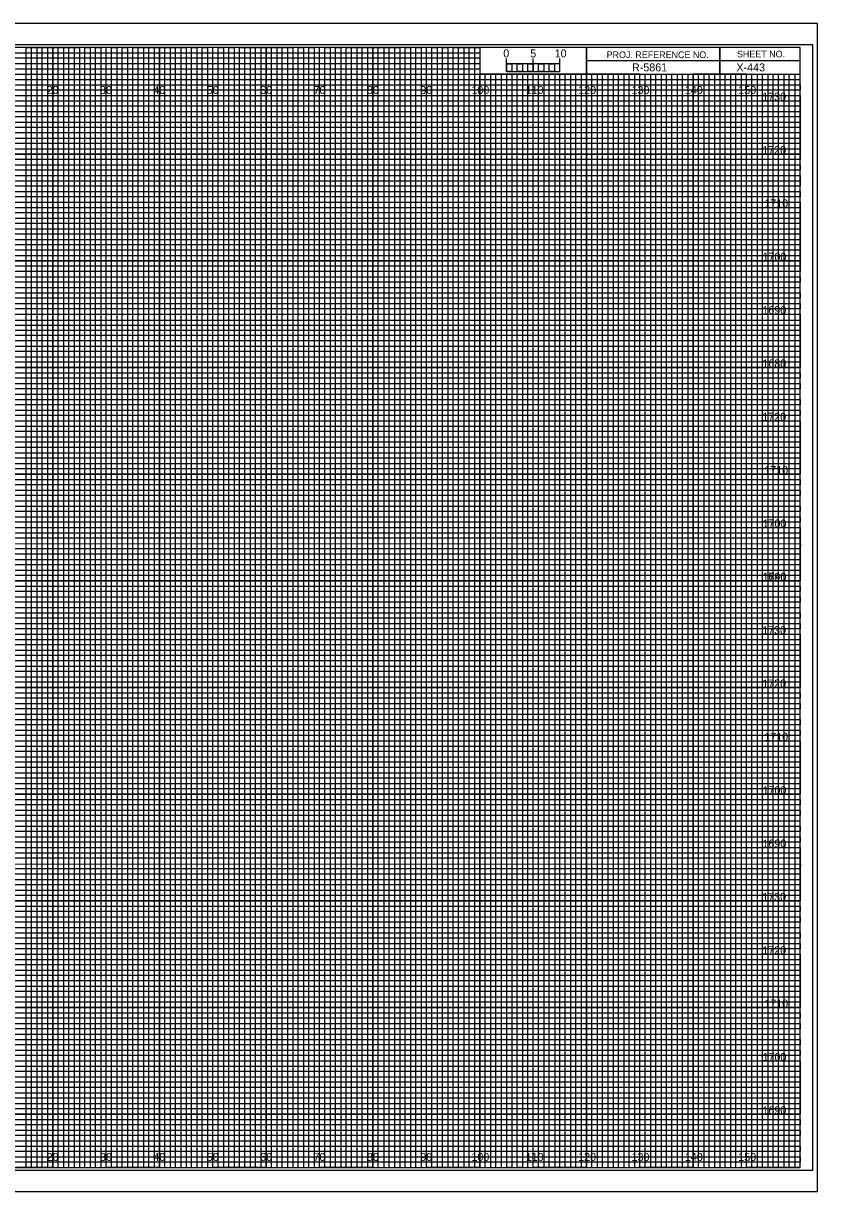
# Model space of a CAD drawing. Extents: x -13 to 323, y -5 to 1314.
# Drawn here: x 174.5 to 323.3, y 435.5 to 654.5 of the extents above; entities that cross this region are included whole.
import ezdxf

# ---------------------------------------------------------------- set-up
doc = ezdxf.new("R2010")
doc.units = 0
for name, color, linetype in [('Prop XS Bar Scale Labels', 7, 'Continuous'), ('Prop XS Project Number', 7, 'Continuous'), ('Prop XS Sheet Number', 7, 'Continuous'), ('Raster_Level_0', 7, 'Continuous'), ('Scratch_Level_3', 7, 'Continuous'), ('Sheet Cross Section CELL', 7, 'Continuous'), ('Sheet Cross Section Grid Major CELL', 7, 'Continuous'), ('Sheet Cross Section Grid Middle CELL', 7, 'Continuous'), ('Sheet Cross Section Grid Minor 1 CELL', 7, 'Continuous'), ('Sheet Cross Section Grid Minor 2 CELL', 7, 'Continuous'), ('Sheet Cross Section Scale CELL', 7, 'Continuous'), ('Sheet Cutting Line CELL', 7, 'Continuous'), ('Sheet DOT Grid CELL', 7, 'Continuous'), ('Sheet Plot Border Inside CELL', 7, 'Continuous'), ('Sheet Plot Border Outside CELL', 7, 'Continuous')]:
    doc.layers.add(name, color=color, linetype=linetype)

msp = doc.modelspace()

# ---------------------------------------------------------------- linework, layer by layer
at = {"layer": 'Sheet Cross Section CELL'}
for p, q in [((305, 650), (305, 645)), ((305, 645), (305, 650)), ((280, 647.5), (280, 645)), ((320, 647.49), (280, 647.49)), ((280, 645), (320, 645))]:
    msp.add_line(p, q, dxfattribs=at)
for points in [[(320, 650), (0, 650), (0, 440), (320, 440)], [(280, 650), (260, 650), (260, 645.03), (280, 645.03)], [(320, 650), (280, 650), (280, 645), (320, 645)]]:
    msp.add_lwpolyline(points, close=True, dxfattribs=at)
at = {"layer": 'Sheet Cross Section Grid Major CELL'}
for p, q in [((190, 650), (180, 650)), ((180, 650), (180, 440)), ((190, 440), (190, 650)), ((210, 650), (200, 650)), ((200, 650), (200, 440)), ((210, 440), (210, 650)), ((230, 650), (220, 650)), ((220, 650), (220, 440)), ((230, 440), (230, 650)), ((250, 650), (240, 650)), ((240, 650), (240, 440)), ((250, 440), (250, 650)), ((260, 650), (260, 440)), ((270, 440), (270, 645)), ((290, 645), (280, 645)), ((280, 645), (280, 440)), ((290, 440), (290, 645)), ((310, 645), (300, 645)), ((300, 645), (300, 440)), ((310, 440), (310, 645)), ((180, 440), (170, 440)), ((200, 440), (190, 440)), ((220, 440), (210, 440)), ((240, 440), (230, 440)), ((260, 440), (250, 440)), ((280, 440), (270, 440)), ((300, 440), (290, 440)), ((320, 440), (310, 440)), ((320, 440), (320, 440))]:
    msp.add_line(p, q, dxfattribs=at)
for points in [[(0, 640), (320, 640), (320, 630), (0, 630)], [(0, 620), (320, 620), (320, 610), (0, 610)], [(0, 600), (320, 600), (320, 590), (0, 590)], [(0, 580), (320, 580), (320, 570), (0, 570)], [(0, 560), (320, 560), (320, 550), (0, 550)], [(0, 540), (320, 540), (320, 530), (0, 530)], [(0, 520), (320, 520), (320, 510), (0, 510)], [(0, 500), (320, 500), (320, 490), (0, 490)], [(0, 480), (320, 480), (320, 470), (0, 470)], [(0, 460), (320, 460), (320, 450), (0, 450)]]:
    msp.add_lwpolyline(points, dxfattribs=at)
at = {"layer": 'Sheet Cross Section Grid Middle CELL'}
for points in [[(165, 440), (175, 440), (175, 650), (185, 650), (185, 440), (195, 440), (195, 650), (205, 650), (205, 440), (215, 440), (215, 650), (225, 650), (225, 440), (235, 440), (235, 650), (245, 650), (245, 440), (255, 440), (255, 650), (259.93, 650), (260, 650), (260, 645), (264.99, 645), (264.99, 440), (275, 440), (275, 645), (285, 645), (285, 440), (295, 440), (295, 645), (305, 645), (305, 440), (315, 440), (315, 645)], [(0, 645), (275, 645)], [(0, 625), (320, 625), (320, 635), (0, 635)], [(0, 605), (320, 605), (320, 615), (0, 615)], [(0, 585), (320, 585), (320, 595), (0, 595)], [(0, 565), (320, 565), (320, 575), (0, 575)], [(0, 545), (320, 545), (320, 555), (0, 555)], [(0, 525), (320, 525), (320, 535), (0, 535)], [(0, 505), (320, 505), (320, 515), (0, 515)], [(0, 485), (320, 485), (320, 495), (0, 495)], [(0, 465), (320, 465), (320, 475), (0, 475)], [(0, 445), (320, 445), (320, 455), (0, 455)]]:
    msp.add_lwpolyline(points, dxfattribs=at)
at = {"layer": 'Sheet Cross Section Grid Minor 1 CELL'}
for p, q in [((0, 649), (260, 649)), ((260, 649), (260, 647.98)), ((260, 647.98), (0, 647.98)), ((0, 647), (260, 647)), ((260, 647), (260, 645.89)), ((260, 645.89), (0, 645.89)), ((0, 644), (320, 644))]:
    msp.add_line(p, q, dxfattribs=at)
for points in [[(0, 643), (270, 643), (320, 643), (320, 642), (0, 642)], [(0, 641), (320, 641), (320, 639), (0, 639)], [(0, 638), (320, 638), (320, 637), (0, 636.98)], [(0, 636), (320, 636), (320, 634), (0, 634)], [(0, 633), (320, 633), (320, 632), (0, 632)], [(0, 631), (320, 631), (320, 629), (0, 629)], [(0, 628), (320, 628), (320, 627), (0, 627)], [(0, 626), (320, 626), (320, 624), (0, 624)], [(0, 623), (320, 623), (320, 622), (0, 622)], [(0, 621), (320, 621), (320, 619), (0, 619)], [(0, 618), (320, 618), (320, 617), (0, 617)], [(0, 616), (320, 616), (320, 613.95), (320, 613), (320, 612), (0, 612)], [(0, 614), (320, 614), (320, 613), (0, 613)], [(0, 611), (320, 611), (320, 609), (0, 609.03)], [(0, 609.03), (320, 609), (320, 608), (0, 608)], [(0, 607), (320, 607), (320, 606), (0, 606)], [(0, 604), (320, 604), (320, 603), (0, 603)], [(0, 602), (320, 602), (320, 601), (0, 601)], [(-0.07, 598.89), (320, 598.89), (320, 597.88), (-0.07, 597.88)], [(0, 597), (320, 597), (320, 596), (0, 596)], [(0, 594), (320, 594), (320, 593), (0, 593)], [(0, 592), (320, 592), (320, 591), (0, 591)], [(0, 589), (320, 589), (320, 588), (0, 588)], [(0, 587), (320, 587), (320, 586), (0, 586)], [(0, 584), (320, 584), (320, 583), (0, 583)], [(0, 582), (320, 582), (320, 581), (0, 581)], [(0, 579), (320, 579), (319.99, 577.98), (0, 578)], [(0, 577), (320, 577), (320, 576), (0, 576)], [(0, 574), (320, 574), (320, 573), (0, 573)], [(0, 572), (320, 572), (320, 571), (0, 571)], [(0, 569), (320, 569), (320, 568), (0, 568)], [(0, 567), (320, 567), (320, 566), (0, 566)], [(0, 564), (320, 564), (320, 563), (0, 563)], [(0, 562), (320, 562), (320, 561), (0, 561)], [(0, 559), (320, 559), (320, 558), (0, 558)], [(0, 556.99), (320.07, 556.91), (320, 556), (0, 556)], [(0, 554), (320, 554), (320, 553), (0, 553)], [(0, 552), (320, 552), (320, 551), (0, 551)], [(0, 549), (320, 549), (320, 548), (0, 548)], [(0, 547), (320, 547), (320, 546), (0, 546)], [(0, 544), (320, 544), (320, 543), (0, 543)], [(0, 542), (320, 542), (320, 541), (0, 541)], [(0, 539), (320, 539), (320, 538), (0, 538)], [(0, 537), (320, 537), (320, 536), (0, 536)], [(0, 534), (320, 534), (320, 533), (0, 533)], [(0, 532), (320, 532), (320, 531), (0, 531)], [(0, 529), (320, 529), (320, 528), (0, 528)], [(0, 527), (320, 527), (320, 526), (0, 526)], [(0, 524), (320, 524), (320, 523), (0, 523)], [(0, 522), (320, 522), (320, 521), (0, 521)], [(0, 519), (320, 519), (319.99, 517.98), (0, 518)], [(0, 517), (320, 517), (320, 516), (0, 516)], [(0, 514), (320, 514), (320, 513), (0, 513)], [(0, 512), (320, 512), (320, 511), (0, 511)], [(0, 509), (320, 509), (320, 508), (0, 508)], [(0, 507), (320, 507), (320, 506), (0, 506)], [(0, 504), (320, 504), (320, 503), (0, 503)], [(0, 502), (320, 502), (320, 501), (0, 501)], [(0, 499), (320, 499), (320, 498), (0, 498)], [(0, 496.99), (320.07, 496.91), (320, 496), (0, 496)], [(0, 494), (320, 494), (320, 493), (0, 493)], [(0, 492), (320, 492), (320, 491), (0, 491)], [(0, 489), (320, 489), (320, 488), (0, 488)], [(0, 487), (320, 487), (320, 486), (0, 486)], [(0, 484), (320, 484), (320, 483), (0, 483)], [(0, 482), (320, 482), (320, 481), (0, 481)], [(0, 479), (320, 479), (320, 478), (0, 478)], [(0, 477), (320, 477), (320, 476), (0, 476)], [(0, 474), (320, 474), (320, 473), (0, 473)], [(0, 472), (320, 472), (320, 471), (0, 471)], [(0, 469), (320, 469), (320, 468), (0, 468)], [(0, 467), (320, 467), (320, 466), (0, 466)], [(0, 464), (320, 464), (320, 463), (0, 463)], [(0, 462), (320, 462), (320, 461), (0, 461)], [(0, 459), (320, 459), (320, 458), (0, 458)], [(0, 457), (320, 457), (320, 456), (0, 456)], [(0, 454), (320, 454), (320, 453), (0, 453)], [(0, 452), (320, 452), (320, 451), (0, 451)], [(0, 449), (320, 449), (320, 448), (0, 448)], [(0, 447), (320, 447), (320, 446), (0, 446)], [(0, 444), (320, 444), (320, 443), (0, 443)], [(0, 442), (320, 442), (320, 441), (0, 441)]]:
    msp.add_lwpolyline(points, dxfattribs=at)
at = {"layer": 'Sheet Cross Section Grid Minor 2 CELL'}
for p, q in [((267, 645), (266.01, 645)), ((266.01, 645), (266.01, 440)), ((267, 440), (267, 645)), ((269, 645), (268, 645)), ((268, 645), (268, 440)), ((269, 440), (269, 645)), ((266.01, 440), (265, 440)), ((268, 440), (267, 440))]:
    msp.add_line(p, q, dxfattribs=at)
for points in [[(175, 440), (176, 440), (176, 650), (177, 650), (177, 440)], [(177, 440), (178, 440), (178, 650), (179, 650), (179, 440)], [(180, 440), (181, 440), (181, 650), (182, 650), (182, 440)], [(182, 440), (183, 440), (183, 650), (184, 650), (184, 440)], [(185, 440), (186, 440), (186, 650), (187, 650), (187, 440)], [(187, 440), (188, 440), (188, 650), (189, 650), (189, 440)], [(190, 440), (191, 440), (191, 650), (192, 650), (192, 440)], [(192, 440), (193, 440), (193, 650), (194, 650), (194, 440)], [(195, 440), (196, 440), (196, 650), (197, 650), (197, 440)], [(197, 440), (198, 440), (198, 650), (199, 650), (199, 440)], [(200, 440), (201, 440), (201, 650), (202, 650), (202, 440)], [(202, 440), (203, 440), (203, 650), (204, 650), (204, 440)], [(205, 440), (206, 440), (206, 650), (207, 650), (207, 440)], [(207, 440), (208, 440), (208, 650), (209, 650), (209, 440)], [(210, 440), (211, 440), (211, 650), (212, 650), (212, 440)], [(212, 440), (213, 440), (213, 650), (214, 650), (214, 440)], [(215, 440), (216, 440), (216, 650), (217, 650), (217, 440)], [(217, 440), (218, 440), (218, 650), (219, 650), (219, 440)], [(220, 440), (221, 440), (221, 650), (222, 650), (222, 440)], [(222, 440), (223, 440), (223, 650), (224, 650), (224, 440)], [(225, 440), (226, 440), (226, 650), (227, 650), (227, 440)], [(227, 440), (228, 440), (228, 650), (229, 650), (229, 440)], [(230, 440), (231, 440), (231, 650), (232, 650), (232, 440)], [(232, 440), (233, 440), (233, 650), (234, 650), (234, 440)], [(235, 440), (236, 440), (236, 650), (237, 650), (237, 440)], [(237, 440), (238, 440), (238, 650), (239, 650), (239, 440)], [(240, 440), (241, 440), (241, 650), (242, 650), (242, 440)], [(242, 440), (243, 440), (243, 650), (244, 650), (244, 440)], [(245, 440), (246, 440), (246, 650), (247, 650), (247, 440)], [(247, 440), (248, 440), (248, 650), (249, 650), (249, 440)], [(250, 440), (251, 440), (251, 650), (252, 650), (252, 440)], [(252, 440), (253, 440), (253, 650), (254, 650), (254, 440)], [(255, 440), (256, 440), (256, 650), (257, 650), (257, 440)], [(257, 440), (258, 440), (258, 650), (259, 650), (259, 440)], [(260, 440), (261, 440), (261, 645), (262.02, 645), (262.02, 440)], [(262, 440), (263, 440), (263, 645), (263.99, 645), (263.99, 440)], [(270, 440), (270.98, 440), (270.98, 645), (272, 645), (272, 440)], [(272, 440), (273, 440), (273, 645), (274.05, 645), (274.05, 440)], [(275, 440), (276, 440), (276, 645), (277, 645), (277, 440)], [(277, 440), (278, 440), (278, 645), (279, 645), (279, 440)], [(280, 440), (281, 440), (281, 645), (282, 645), (282, 440)], [(282, 440), (283, 440), (283, 645), (284, 645), (284, 440)], [(285, 440), (286, 440), (286, 645), (287, 645), (287, 440)], [(287, 440), (288, 440), (288, 645), (289, 645), (289, 440)], [(290, 440), (291, 440), (291, 645), (292, 645), (292, 440)], [(292, 440), (293, 440), (293, 645), (294, 645), (294, 440)], [(295, 440), (296, 440), (296, 645), (297, 645), (297, 440)], [(297, 440), (298, 440), (298, 645), (299, 645), (299, 440)], [(300, 440), (301, 440), (301, 645), (302, 645), (302, 440)], [(302, 440), (303, 440), (303, 645), (304, 645), (304, 440)], [(305, 440), (306, 440), (306, 645), (307, 645), (307, 440)], [(307, 440), (308, 440), (308, 645), (309, 645), (309, 440)], [(310, 440), (311, 440), (311, 645), (312, 645), (312, 440)], [(312, 440), (313, 440), (313, 645), (314, 645), (314, 440)], [(315, 440), (316, 440), (316, 645), (317, 645), (317, 440)], [(317, 440), (318, 440), (318, 645), (319, 645), (319, 440)]]:
    msp.add_lwpolyline(points, dxfattribs=at)
at = {"layer": 'Sheet Cross Section Scale CELL'}
for p, q in [((265, 645.49), (265, 647.9)), ((265, 646.9), (265, 647.9)), ((270, 645.49), (270, 647.9)), ((275, 645.49), (275, 647.9)), ((275, 646.9), (275, 647.9))]:
    msp.add_line(p, q, dxfattribs=at)
for points in [[(275, 646.9), (265, 646.9), (265, 645.49), (275, 645.49)], [(265, 646.9), (266, 646.9), (266, 645.49), (265, 645.49)], [(267, 646.9), (268, 646.9), (268, 645.49), (267, 645.49)], [(269, 646.9), (270, 646.9), (270, 645.49), (269, 645.49)], [(271, 646.9), (272, 646.9), (272, 645.49), (271, 645.49)], [(273, 646.9), (274, 646.9), (274, 645.49), (273, 645.49)]]:
    msp.add_lwpolyline(points, close=True, dxfattribs=at)
at = {"layer": 'Sheet Cutting Line CELL'}
for p, q in [((323.3, 654.5), (-13.4, 654.5)), ((-13.4, 435.5), (323.3, 435.5))]:
    msp.add_line(p, q, dxfattribs=at)
at = {"layer": 'Sheet DOT Grid CELL'}
for p, q in [((180, 440), (180, 650)), ((190, 440), (190, 650)), ((200, 440), (200, 650)), ((210, 440), (210, 650)), ((220, 440), (220, 650)), ((230, 440), (230, 650)), ((240, 440), (240, 650)), ((250, 440), (250, 650)), ((260, 440), (260, 644.69)), ((270, 440), (270, 644.69)), ((280, 440), (280, 644.69)), ((290, 440), (290, 644.69)), ((300, 440), (300, 644.69)), ((310, 440), (310, 644.69)), ((0, 640), (320, 640)), ((0, 630), (320, 630)), ((0, 620), (320, 620)), ((0, 610), (320, 610)), ((0, 600), (320, 600)), ((0, 590), (320, 590)), ((0, 580), (320, 580)), ((0, 570), (320, 570)), ((0, 560), (320, 560)), ((0, 550), (320, 550)), ((0, 540), (320, 540)), ((0, 530), (320, 530)), ((0, 520), (320, 520)), ((0, 510), (320, 510)), ((0, 500), (320, 500)), ((0, 490), (320, 490)), ((0, 480), (320, 480)), ((0, 470), (320, 470)), ((0, 460), (320, 460)), ((0, 450), (320, 450))]:
    msp.add_line(p, q, dxfattribs=at)
at = {"layer": 'Sheet Plot Border Inside CELL'}
msp.add_lwpolyline([(-10.8, 439.5), (322.4, 439.5), (322.4, 650.5), (-10.8, 650.5)], close=True, dxfattribs=at)
at = {"layer": 'Sheet Plot Border Outside CELL'}
msp.add_lwpolyline([(-13.4, 435.5), (323.3, 435.5), (323.3, 654.5), (-13.4, 654.5)], close=True, dxfattribs=at)

# ---------------------------------------------------------------- texts
at = {"layer": 'Prop XS Bar Scale Labels'}
for s, p in [('5', (269.47, 648.12)), ('10', (274.04, 648.12))]:
    msp.add_text(s, height=1.5, dxfattribs=at).set_placement(p)
at = {"layer": 'Prop XS Project Number'}
msp.add_text('R-5861', height=1.5, dxfattribs=at).set_placement((288.53, 645.5))
at = {"layer": 'Prop XS Sheet Number'}
msp.add_text('X-443', height=1.5, dxfattribs=at).set_placement((308.09, 645.5))
at = {"layer": 'Raster_Level_0'}
for s, p in [('20', (178.86, 641.25)), ('30', (188.86, 641.25)), ('40', (198.86, 641.25)), ('50', (208.86, 641.25)), ('60', (218.86, 641.25)), ('70', (228.86, 641.25)), ('80', (238.86, 641.25)), ('90', (248.86, 641.25)), ('100', (258.44, 641.25)), ('110', (268.62, 641.25)), ('120', (278.44, 641.25)), ('130', (288.44, 641.25)), ('140', (298.44, 641.25)), ('150', (308.44, 641.25)), ('20', (178.86, 441.25)), ('30', (188.86, 441.25)), ('40', (198.86, 441.25)), ('50', (208.86, 441.25)), ('60', (218.86, 441.25)), ('70', (228.86, 441.25)), ('80', (238.86, 441.25)), ('90', (248.86, 441.25)), ('100', (258.44, 441.25)), ('110', (268.62, 441.25)), ('120', (278.44, 441.25)), ('130', (288.44, 441.25)), ('140', (298.44, 441.25)), ('150', (308.44, 441.25))]:
    msp.add_text(s, height=1.5, dxfattribs=at).set_placement(p)
at = {"layer": 'Scratch_Level_3'}
for s, p in [('1730', (312.92, 640)), ('1720', (312.93, 630)), ('1710', (313.31, 620)), ('1700', (312.98, 610)), ('1690', (312.97, 600)), ('1680', (312.95, 590)), ('1720', (312.93, 580)), ('1710', (313.31, 570)), ('1700', (312.98, 560)), ('1690', (312.97, 550)), ('1740', (313, 550)), ('1730', (312.92, 540)), ('1720', (312.93, 530)), ('1710', (313.31, 520)), ('1700', (312.98, 510)), ('1690', (312.97, 500)), ('1730', (312.92, 490)), ('1720', (312.93, 480)), ('1710', (313.31, 470)), ('1700', (312.98, 460)), ('1690', (312.97, 450))]:
    msp.add_text(s, height=1.5, dxfattribs=at).set_placement(p)
at = {"layer": 'Sheet Cross Section CELL'}
for s, p in [('PROJ. REFERENCE NO.', (283.77, 647.99)), ('SHEET NO.', (308.19, 648.12))]:
    msp.add_text(s, height=1.25, dxfattribs=at).set_placement(p)
at = {"layer": 'Sheet Cross Section Scale CELL'}
msp.add_text('0', height=1.5, dxfattribs=at).set_placement((264.41, 648.12))

doc.saveas('drawing.dxf')
